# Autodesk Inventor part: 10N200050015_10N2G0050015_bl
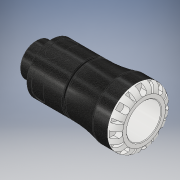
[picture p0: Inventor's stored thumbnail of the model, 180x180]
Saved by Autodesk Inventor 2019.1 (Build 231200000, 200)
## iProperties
Created: 2016-12
Part Number: 10N200050015_10N2G0050015_bl
Material: PVC-Piping
Description: PLASSON MALE ADAPTOR 50X1.1/2" SERIES 1
Document SubType Name: Modeling
Designer: KIM
Mass: 61.7504 g
Surface Area: 140.097 cm^2
Volume: 44.1074 cm^3
Density: 1.4 g/cm^3
Appearance: Black Cast
Author: KIM
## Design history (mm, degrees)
derived "10N20.ipt"
feature "Solid1::10N20.ipt" dims "ScaleForDerivedMember" = 10
tag "TaggingFeature1"
body "Solid1"
other parameters: "d0" = 158 [user parameter], "d1" = 32.76 [user parameter], "d3" = 62.5 [user parameter], "d4" = 85 [user parameter], "d6" = 78 [user parameter], "d8" = 72.25 [user parameter], "d13" = 9 [user parameter], "d14" = 9 [user parameter], "d15" = 0 [user parameter], "d17" = 360 deg [user parameter], "d19" = 8 deg [user parameter], "d20" = 1 [user parameter], "d21" = 1 [user parameter], "d22" = 8 deg [user parameter], "d24" = 0 [user parameter], "d26" = 360 deg [user parameter], "d32" = 0.925 [user parameter], "d33" = 8.5 [user parameter], "d34" = 47.803 [user parameter], "d35" = 6.25 [user parameter], "d38" = 22 [user parameter], "d39" = 1.43409 [user parameter], "d42" = 17.5 [user parameter], "d43" = 11.5 [user parameter], "d45" = 17.64 [user parameter], "d46" = 0 [user parameter], "d59" = 360 deg [user parameter], "d61" = 14.875 [user parameter], "d62" = 1 [user parameter], "d64" = 0 [user parameter], "d65" = 0.85 [user parameter], "d69" = 2 [user parameter], "d70" = 2.37 [user parameter], "d71" = 3 [user parameter], "d73" = 1 [user parameter], "E_" = 85 [user parameter], "H_" = 158 [user parameter], "l_" = 78 [user parameter], "R_" = 47.803 [user parameter], "l_2" = 22 [user parameter], "d9" = 11.25 [user parameter], "d11" = 85 [user parameter], "d12" = 62.5 [user parameter]
